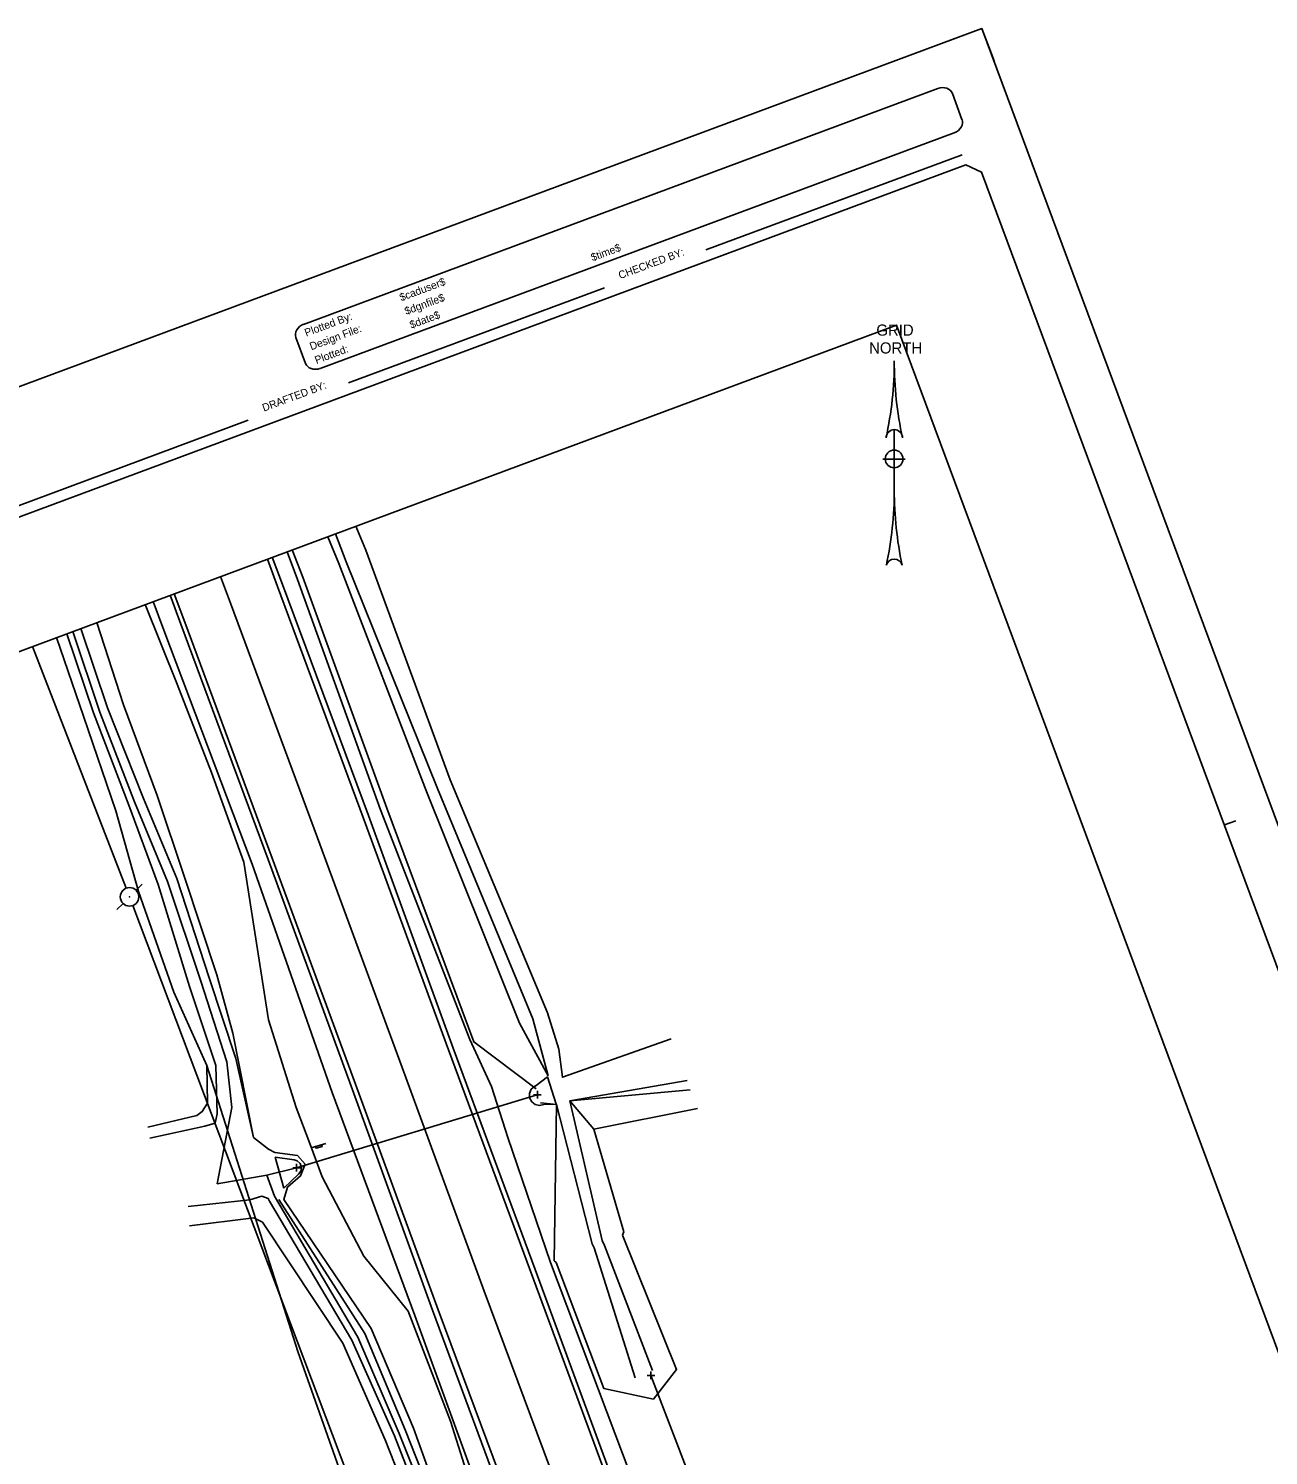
# Model space of a CAD drawing. Extents: x 1040172 to 1040822, y 1127790 to 1128580.
# Drawn here: x 1040389.4 to 1040643.1, y 1128288.4 to 1128580.3 of the extents above; entities that cross this region are included whole.
import ezdxf

# ---------------------------------------------------------------- set-up
doc = ezdxf.new("R2010")
doc.units = 0
for name, color, linetype in [('clip boundary', 7, 'Continuous'), ('DCP', 7, 'Continuous'), ('DD', 7, 'Continuous'), ('DELB', 7, 'Continuous'), ('DES', 7, 'Continuous'), ('DINV', 7, 'Continuous'), ('LABL', 7, 'Continuous'), ('LELB', 7, 'Continuous'), ('NBS_P', 7, 'Continuous'), ('NBS_P_T', 7, 'Continuous'), ('NNA_P', 7, 'Continuous'), ('PE', 7, 'Continuous'), ('RDU', 7, 'Continuous'), ('SDEL', 7, 'Continuous'), ('SHEET_BORDER', 7, 'Continuous'), ('SHEET_BORDER_CUT', 7, 'Continuous'), ('SHEET_BORDER_TEXT', 7, 'Continuous'), ('STPBY', 7, 'Continuous'), ('STSEW', 7, 'Continuous'), ('UEO', 7, 'Continuous'), ('UP', 7, 'Continuous')]:
    doc.layers.add(name, color=color, linetype=linetype)

msp = doc.modelspace()

# ---------------------------------------------------------------- linework, layer by layer
at = {"layer": 'clip boundary'}
for points in [[(1040584.48, 1128580.33), (1040821.52, 1127942.99), (1040409.12, 1127789.61), (1040172.08, 1128426.95)], [(1040311.42, 1128424.61), (1040504.79, 1127904.67), (1040760.34, 1127999.71), (1040566.96, 1128519.66)]]:
    msp.add_lwpolyline(points, close=True, dxfattribs=at)
at = {"layer": 'DCP'}
for p, q in [((1040444.24, 1128347.29), (1040493.5, 1128362.18)), ((1040516.73, 1128304.75), (1040524.64, 1128284.21))]:
    msp.add_line(p, q, dxfattribs=at)
at = {"layer": 'DD'}
for points in [[(1040431.03, 1128359.61), (1040429.95, 1128368.94), (1040424.68, 1128385.43), (1040417.81, 1128405.81), (1040411.06, 1128422.12), (1040403.99, 1128440.48), (1040398.47, 1128456.99)], [(1040431.03, 1128359.61), (1040428.01, 1128343.96)], [(1040590.16, 1127936.41), (1040584.34, 1127954.8), (1040577.73, 1127972.42), (1040570.66, 1127991.71), (1040562.32, 1128013.81), (1040557.05, 1128034.44), (1040549.61, 1128054.25), (1040542.46, 1128077.69), (1040533.08, 1128100.98), (1040522.95, 1128126.72), (1040518.21, 1128143.72), (1040509.19, 1128174.67), (1040500.96, 1128197.49), (1040493.5, 1128216.61), (1040486.01, 1128239.31), (1040476.77, 1128264.06), (1040465.21, 1128292.91), (1040456.76, 1128312.61), (1040439.7, 1128341.45), (1040438.14, 1128345.77)]]:
    msp.add_lwpolyline(points, dxfattribs=at)
at = {"layer": 'DELB'}
for points in [[(1040495.7, 1128366.09), (1040489.88, 1128376.85), (1040470.85, 1128424.23), (1040452.9, 1128470.87), (1040450.61, 1128476.38)], [(1040495.7, 1128366.09), (1040492.59, 1128377.73), (1040473.08, 1128424.83), (1040454.38, 1128471.2), (1040452.18, 1128476.97)], [(1040520.86, 1128373.67), (1040498.64, 1128365.78), (1040497.9, 1128371.56), (1040495.55, 1128379), (1040475.67, 1128426.66), (1040458.43, 1128473.59), (1040456.39, 1128478.53)], [(1040493.26, 1128363.4), (1040480.53, 1128373.01), (1040462.72, 1128420.84), (1040445.51, 1128468.09), (1040443.37, 1128473.69)], [(1040524.18, 1128365.14), (1040500.16, 1128360.99)], [(1040511.21, 1128334.14), (1040505.05, 1128355.2), (1040500.16, 1128360.99), (1040524.75, 1128363.2)], [(1040504.74, 1128331.73), (1040497.43, 1128360.25), (1040494.13, 1128360.53)], [(1040496.95, 1128328.24), (1040497.43, 1128360.25)], [(1040506.78, 1128332.38), (1040500.16, 1128360.99)], [(1040526.27, 1128359.42), (1040505.05, 1128355.2)], [(1040444.24, 1128347.29), (1040438.14, 1128345.77), (1040428.01, 1128343.96)], [(1040510.96, 1128333.48), (1040511.21, 1128334.14)], [(1040517.27, 1128299.94), (1040521.98, 1128305.99), (1040510.96, 1128333.48)], [(1040505.13, 1128330.89), (1040504.74, 1128331.73)], [(1040513.55, 1128304.31), (1040505.13, 1128330.89)], [(1040507.28, 1128331.34), (1040506.78, 1128332.38)], [(1040517.09, 1128305.79), (1040507.28, 1128331.34)], [(1040497.36, 1128327.89), (1040496.95, 1128328.24)], [(1040517.27, 1128299.94), (1040507.1, 1128302.15), (1040497.36, 1128327.89)]]:
    msp.add_lwpolyline(points, dxfattribs=at)
at = {"layer": 'DES'}
msp.add_line((1040439.89, 1128349.41), (1040441.65, 1128343.07), dxfattribs=at)
for points in [[(1040495.6, 1128365.88), (1040497.38, 1128360.28), (1040494.85, 1128360.25), (1040493.97, 1128360.04), (1040493.08, 1128360.22), (1040492.35, 1128360.77), (1040491.93, 1128361.57), (1040491.88, 1128362.48), (1040492.23, 1128363.32), (1040492.9, 1128363.93), (1040493.25, 1128364.09), (1040495.6, 1128365.88)], [(1040441.65, 1128343.07), (1040444.61, 1128345.97), (1040445.1, 1128346.6), (1040445.23, 1128347.39), (1040444.97, 1128348.15), (1040444.38, 1128348.69), (1040443.73, 1128348.88), (1040439.89, 1128349.41)]]:
    msp.add_lwpolyline(points, dxfattribs=at)
at = {"layer": 'DINV'}
for p, q in [((1040493.51, 1128362.22), (1040493.51, 1128363.01)), ((1040493.51, 1128362.22), (1040492.73, 1128362.22)), ((1040493.51, 1128362.22), (1040494.3, 1128362.22)), ((1040493.51, 1128362.22), (1040493.51, 1128361.43)), ((1040444.24, 1128347.29), (1040444.24, 1128348.08)), ((1040444.24, 1128347.29), (1040443.46, 1128347.29)), ((1040444.24, 1128347.29), (1040445.03, 1128347.29)), ((1040444.24, 1128347.29), (1040444.24, 1128346.5)), ((1040516.75, 1128304.78), (1040515.96, 1128304.78)), ((1040516.75, 1128304.78), (1040516.75, 1128305.57)), ((1040516.75, 1128304.78), (1040517.53, 1128304.78)), ((1040516.75, 1128304.78), (1040516.75, 1128304))]:
    msp.add_line(p, q, dxfattribs=at)
at = {"layer": 'LABL'}
for points in [[(1040395.11, 1128455.74), (1040400.67, 1128439.67), (1040407.29, 1128420.28), (1040411.93, 1128403.77), (1040419.1, 1128383.22), (1040425.91, 1128368.18)], [(1040425.91, 1128368.18), (1040444.53, 1128309.71), (1040463.02, 1128257.15), (1040477.81, 1128216.23), (1040494.07, 1128178.95), (1040522.79, 1128098.94), (1040535.3, 1128073.89), (1040559.97, 1128013.01), (1040568.12, 1127991.17), (1040574.76, 1127971.48), (1040581.61, 1127953.82), (1040587.68, 1127935.49)]]:
    msp.add_lwpolyline(points, dxfattribs=at)
at = {"layer": 'LELB'}
for points in [[(1040524.19, 1128157.24), (1040518.18, 1128177.19), (1040509.58, 1128200.97), (1040503.44, 1128219.77), (1040494.26, 1128243.13), (1040484.62, 1128267.31), (1040475.77, 1128295.4), (1040467.07, 1128317.96), (1040457.98, 1128329.2), (1040449.47, 1128345.43), (1040446.95, 1128352.21), (1040444.14, 1128359.62), (1040438.48, 1128377.55), (1040433.46, 1128409.8), (1040426.84, 1128428.17), (1040419.78, 1128446.21), (1040413.29, 1128462.5)], [(1040478.6, 1128264.98), (1040468.18, 1128294), (1040459.51, 1128314.41), (1040441.65, 1128340.8), (1040442.42, 1128343.33), (1040445.06, 1128345.62), (1040446, 1128348.03), (1040444.41, 1128349.76), (1040439.8, 1128350.37), (1040438.5, 1128351.11), (1040435.45, 1128353.48), (1040431.19, 1128374.8), (1040427.91, 1128386.72), (1040421.28, 1128406.71), (1040415.74, 1128423.43), (1040408.85, 1128441.96), (1040403.4, 1128458.83)], [(1040414.19, 1128353.31), (1040425.46, 1128355.75), (1040427.61, 1128356.37), (1040428.02, 1128358.31), (1040427.69, 1128368.18), (1040422.35, 1128384.38), (1040415.95, 1128405.22), (1040409.95, 1128421.48), (1040402.66, 1128440.32), (1040397.23, 1128456.53)], [(1040435.45, 1128353.48), (1040431.79, 1128369.62), (1040426.38, 1128386.15), (1040419.75, 1128406.47), (1040412.9, 1128422.8), (1040405.58, 1128441.34), (1040400.08, 1128457.59)], [(1040413.79, 1128355.58), (1040423.84, 1128358), (1040424.94, 1128358.76), (1040426.04, 1128360.47), (1040425.91, 1128368.18), (1040419.1, 1128383.22), (1040411.93, 1128403.77), (1040407.29, 1128420.28), (1040400.67, 1128439.67), (1040395.11, 1128455.74)], [(1040562.32, 1128013.81), (1040556.06, 1128033.92), (1040548.57, 1128053.68), (1040541.49, 1128077.3), (1040531.67, 1128100.43), (1040520.61, 1128126.06), (1040516.58, 1128143.34), (1040506.89, 1128174.28), (1040498.03, 1128196.84), (1040490.79, 1128215.69), (1040483.27, 1128238.22), (1040475.53, 1128263.46), (1040464.25, 1128292.43), (1040455.52, 1128312.02), (1040438.72, 1128340.45), (1040438.45, 1128340.97), (1040437.13, 1128341.43), (1040434.71, 1128340.72), (1040422.09, 1128339.34)], [(1040494.64, 1128217.07), (1040487.54, 1128240.23), (1040477.97, 1128264.47), (1040466.44, 1128293.63), (1040458.2, 1128313.37), (1040440.59, 1128340.8)], [(1040554.52, 1128033.3), (1040547.08, 1128053.47), (1040539.58, 1128076.27), (1040529.8, 1128099.73), (1040518.96, 1128125.65), (1040515.08, 1128142.88), (1040473.71, 1128262.92), (1040462.39, 1128291.59), (1040453.72, 1128311.36), (1040437.26, 1128336.15), (1040435.49, 1128337), (1040422.35, 1128335.42)]]:
    msp.add_lwpolyline(points, dxfattribs=at)
at = {"layer": 'NBS_P'}
for p, q in [((1040575.45, 1128568.08), (1040445.69, 1128519.82)), ((1040580.39, 1128561.74), (1040578.42, 1128567.05)), ((1040449.06, 1128510.76), (1040578.82, 1128559.03)), ((1040444.1, 1128517.1), (1040446.06, 1128511.83))]:
    msp.add_line(p, q, dxfattribs=at)
for centre, major_axis, start_param, end_param in [((1040576.15, 1128566.21), (2.27, 0.84), 0, 1.570796), ((1040578.13, 1128560.9), (2.27, 0.84), 4.712389, 6.283185), ((1040446.38, 1128517.95), (-2.27, -0.84), 4.712389, 6.283185), ((1040448.34, 1128512.68), (-2.27, -0.84), 0, 1.570796)]:
    msp.add_ellipse(centre, major_axis=major_axis, ratio=0.825959, start_param=start_param, end_param=end_param, dxfattribs=at)
at = {"layer": 'NNA_P'}
for p, q in [((1040566.54, 1128485.91), (1040566.54, 1128498.28)), ((1040564.21, 1128492.26), (1040568.75, 1128492.26))]:
    msp.add_line(p, q, dxfattribs=at)
msp.add_circle((1040566.51, 1128492.28), 1.81, dxfattribs=at)
for centre, radius, start, end in [((1040493.45, 1128512.22), 73.09, 347.6515, 0.1139), ((1040639.62, 1128512.22), 73.09, 179.8844, 192.3468), ((1040566.54, 1128496.59), 1.69, 359.9991, 179.9991), ((1040493.45, 1128485.89), 73.09, 347.8917, 0.0159), ((1040639.62, 1128485.88), 73.09, 179.9824, 192.1066), ((1040566.53, 1128470.09), 1.69, 15.894, 164.1052)]:
    msp.add_arc(centre, radius, start, end, dxfattribs=at)
at = {"layer": 'PE'}
for points in [[(1040439.24, 1128472.16), (1040441.33, 1128466.57), (1040458.94, 1128419.35), (1040476.26, 1128371.77), (1040493.04, 1128326.48), (1040510.61, 1128278.87), (1040527.62, 1128233.22), (1040545.23, 1128186.41), (1040562.42, 1128139.9), (1040579.67, 1128093.09), (1040596.97, 1128046.17), (1040614.6, 1127999.47), (1040632.03, 1127952.66), (1040632.25, 1127952.07)], [(1040611.22, 1127944.25), (1040611.04, 1127944.71), (1040593.69, 1127991.31), (1040575.95, 1128038.43), (1040558.63, 1128085.25), (1040541.53, 1128131.54), (1040524.14, 1128178.42), (1040506.77, 1128224.73), (1040489.58, 1128270.79), (1040472.04, 1128318.16), (1040455.43, 1128363.98), (1040438.41, 1128410.32), (1040420.58, 1128458.47), (1040418.37, 1128464.39)]]:
    msp.add_lwpolyline(points, dxfattribs=at)
at = {"layer": 'RDU'}
for points in [[(1040442.34, 1128473.31), (1040444.42, 1128467.6), (1040461.41, 1128420.47), (1040479.69, 1128373.54), (1040484.11, 1128363.91), (1040487.49, 1128353.45), (1040496.23, 1128327.89), (1040514.27, 1128279.94), (1040530.58, 1128234.37), (1040548.36, 1128187.4), (1040565.14, 1128141.04), (1040582.73, 1128094.4), (1040600.59, 1128047.69), (1040609.21, 1128026.55), (1040611.78, 1128023.8), (1040620.64, 1128002.21), (1040638.45, 1127955.04), (1040638.78, 1127954.5)], [(1040600.82, 1127940.38), (1040598.84, 1127946.51), (1040597.95, 1127949.62), (1040587.15, 1127989.28), (1040571.28, 1128036.76), (1040553.79, 1128083.5), (1040537.46, 1128130.34), (1040520.2, 1128176.84), (1040503.11, 1128223.36), (1040485.75, 1128269.45), (1040468.45, 1128317.03), (1040451.55, 1128362.66), (1040435.14, 1128409.38), (1040417.07, 1128457.26), (1040414.87, 1128463.09)]]:
    msp.add_lwpolyline(points, dxfattribs=at)
at = {"layer": 'SDEL'}
msp.add_line((1040450.24, 1128352.26), (1040447.22, 1128351.34), dxfattribs=at)
msp.add_lwpolyline([(1040448.12, 1128351.61), (1040449.34, 1128351.98), (1040449.45, 1128351.62), (1040448.23, 1128351.25)], close=True, dxfattribs=at)
at = {"layer": 'SHEET_BORDER'}
for p, q in [((1040528, 1128535.03), (1040580.41, 1128554.53)), ((1040454.84, 1128507.82), (1040507.25, 1128527.32)), ((1040381.96, 1128480.72), (1040434.37, 1128500.21)), ((1040634.08, 1128417.4), (1040636.42, 1128418.27))]:
    msp.add_line(p, q, dxfattribs=at)
msp.add_lwpolyline([(1040412.42, 1127817.51), (1040409.2, 1127818.98), (1040191.33, 1128404.77), (1040192.81, 1128407.99), (1040581.19, 1128552.44), (1040584.4, 1128550.96), (1040802.27, 1127965.17), (1040800.8, 1127961.95)], close=True, dxfattribs=at)
at = {"layer": 'SHEET_BORDER_CUT'}
msp.add_lwpolyline([(1040172.08, 1128426.95), (1040409.12, 1127789.61), (1040821.52, 1127942.99), (1040584.48, 1128580.33)], close=True, dxfattribs=at)
msp.add_lwpolyline([(1040577.86, 1128577.87), (1040584.48, 1128580.33), (1040586.95, 1128573.71)], dxfattribs=at)
at = {"layer": 'STPBY'}
msp.add_lwpolyline([(1040621.67, 1127948.13), (1040621.55, 1127948.45), (1040603.98, 1127995.3), (1040586.61, 1128042.26), (1040569.27, 1128089.08), (1040551.95, 1128135.59), (1040534.57, 1128182.32), (1040517.18, 1128229.1), (1040500.26, 1128274.64), (1040482.6, 1128322.04), (1040465.84, 1128367.81), (1040448.53, 1128414.76), (1040430.74, 1128462.77), (1040428.7, 1128468.23)], dxfattribs=at)
at = {"layer": 'STSEW'}
for points in [[(1040438.27, 1128471.79), (1040440.35, 1128466.17), (1040457.9, 1128418.91), (1040475.34, 1128371.42), (1040492.13, 1128326.1), (1040509.73, 1128278.49), (1040526.79, 1128232.92), (1040544.25, 1128186.02), (1040561.46, 1128139.5), (1040578.77, 1128092.69), (1040596.13, 1128045.88), (1040613.59, 1127999.12), (1040631.02, 1127952.26), (1040631.23, 1127951.69)], [(1040612.07, 1127944.56), (1040611.89, 1127945.04), (1040594.53, 1127991.69), (1040577, 1128038.8), (1040559.65, 1128085.64), (1040542.56, 1128131.85), (1040525.02, 1128178.93), (1040507.92, 1128225.11), (1040490.75, 1128271.15), (1040473.24, 1128318.19), (1040456.29, 1128364.36), (1040439.27, 1128410.63), (1040421.37, 1128458.89), (1040419.2, 1128464.7)]]:
    msp.add_lwpolyline(points, dxfattribs=at)
at = {"layer": 'UEO'}
for points in [[(1040390.24, 1128453.93), (1040409.39, 1128404.46)], [(1040410.74, 1128400.93), (1040480.95, 1128214.9)]]:
    msp.add_lwpolyline(points, dxfattribs=at)
at = {"layer": 'UP'}
for p, q in [((1040411.4, 1128404.04), (1040412.65, 1128405.3)), ((1040408.74, 1128401.36), (1040407.49, 1128400.1)), ((1040410.13, 1128402.7), (1040410.01, 1128402.7)), ((1040410.07, 1128402.76), (1040410.07, 1128402.64))]:
    msp.add_line(p, q, dxfattribs=at)
msp.add_circle((1040410.07, 1128402.7), 1.89, dxfattribs=at)

# ---------------------------------------------------------------- texts
at = {"layer": 'NBS_P_T'}
for s, height, p in [('$time$', 1.576, (1040504.82, 1128532.7)), ('$caduser$', 1.576, (1040465.65, 1128524.52)), ('$dgnfile$', 1.576, (1040466.69, 1128521.72)), ('Plotted By:', 1.5759, (1040446.22, 1128517.3)), ('$date$', 1.576, (1040467.73, 1128518.91)), ('Design File:', 1.5759, (1040447.26, 1128514.49)), ('Plotted:', 1.576, (1040448.31, 1128511.69))]:
    msp.add_text(s, height=height, rotation=20.4015, dxfattribs=at).set_placement(p)
at = {"layer": 'NNA_P'}
for s, p in [('GRID', (1040562.87, 1128517.5)), ('NORTH', (1040561.39, 1128513.85))]:
    msp.add_text(s, height=2.283, rotation=359.9991, dxfattribs=at).set_placement(p)
at = {"layer": 'SHEET_BORDER_TEXT'}
for s, p in [('CHECKED BY:', (1040510.44, 1128529.06)), ('DRAFTED BY:', (1040437.56, 1128501.95))]:
    msp.add_text(s, height=1.5625, rotation=20.4011, dxfattribs=at).set_placement(p)

doc.saveas('drawing.dxf')
